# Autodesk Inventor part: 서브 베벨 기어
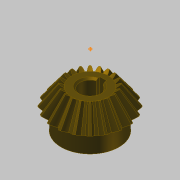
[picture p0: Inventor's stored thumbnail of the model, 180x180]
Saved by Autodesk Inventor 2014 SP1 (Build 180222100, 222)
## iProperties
Created: 2016-04
Part Number: 서브 베벨 기어
Material: 강철, 탄소
Document SubType Name: Modeling
Designer: mdu
Categories: <?xml version="1.0" encoding="UTF-16"?> <MemberInstance><Categories><FamilyTemplate><FamilyTemplateParameter ValueType="xs:double" Id="1" ObjectReferenceKey="da
Mass: 135.037 g
Surface Area: 63.6518 cm^2
Volume: 17.1585 cm^3
Density: 7.87 g/cm^3
Appearance: 얼룩무늬
CustomPartVersion: 1
Author: mdu
Revision Number: 1
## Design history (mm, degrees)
node "맨 위 점"
node "메쉬 평면2"
sketch "톱니 본체 스케치"
  geometry: L1 (0, 0)-(18.003, -31.331); L2 (18.003, -31.331)-(21.664, -28.891); L3 (21.664, -28.891)-(0, 0); L4 (20, -30)-(0, 0); L5 (10.813, -18.818)-(13.012, -17.352); L6 (18.003, -31.331)-(10.813, -18.818); L7 (21.664, -28.891)-(13.012, -17.352); L8 (0, -39.387)-(0, 6.564) reference; L9 (0, -30)-(21.664, -30)
  constraints: 16 end point, 4 point on line, 3 perpendicular, 2 collinear, 1 horizontal alignment, 1 vertical alignment
  dimensions: "d0" = 40 diameter of L4.start L8 (= da_de); "d1" = 36.00616 diameter of L1.end L8 (= da_dfe); "d2" = 43.3282 diameter of L2.end L8 (= da_dae); "d3" = 14.4 distance between parallel lines of L2 L5 (= da_b); "d4" = 28.8906 vertical distance of L2.end L1.start (= da_ve)
revolve "톱니 본체" sketch "톱니 본체 스케치" stored, may be unused: angle "d5" = 90 deg
node "시작점"
node "톱니 평면"
sketch "시작 스케치"
  geometry: L1 (0, -23.505)-(0, 10.645) reference; L2 (-0.834, -2.928)-(0.834, -2.928); A1 r 8.898 centre (-9.698, -3.713) between (-0.834, -2.928) and (-3.903, 3.04); A2 r 8.898 centre (9.698, -3.713) between (3.903, 3.04) and (0.834, -2.928); A3 r 27.357 centre (0, -24.037) between (3.903, 3.04) and (-3.903, 3.04); 1 further point
  constraints: 6 point on circle, 3 centre point, 3 symmetric about line, 2 end point, 1 coincident, 1 perpendicular, 1 other
  dimensions: "d7" = 8.89846 radius of A1 (= fd_rr); "d8" = 9.69794 horizontal distance of point (0, -24.037) A1.centre (= fd_x); "d9" = 20.32439 vertical distance of point (0, -24.037) A1.centre (= fd_y); "d57" = 27.35701 radius of A3 (= 0.5 x fd_dva + 0.3 x da_he); "d58" = 21.10901 distance from line of A3.centre L2 (= 0.5 x fd_dva - 1.12 x da_he)
node "끝점"
  node "끝 평면"
sketch "3D 스케치 오른쪽"
  node "Helical Curve Right" dims "d65" = 229.90621 (computed from da_dm, da_delta, da_beta), "d66" = 31.5, "d67" = 40 (= da_de), "d68" = -5.88003 (= -da_delta), "d69" = 12.16458 (computed from fd_loft, da_delta)
node "끝 평면 오른쪽"
sketch "끝 스케치 오른쪽"
  geometry: L1 (0, -22.649)-(0, 12.15) reference; L2 (-0.497, -1.72)-(0.497, -1.72); A1 r 5.299 centre (-5.775, -2.187) between (-0.497, -1.72) and (-2.324, 1.834); A2 r 5.299 centre (5.775, -2.187) between (2.324, 1.834) and (0.497, -1.72); A3 r 16.291 centre (0, -14.29) between (2.324, 1.834) and (-2.324, 1.834); 1 further point
  constraints: 6 point on circle, 3 centre point, 3 symmetric about line, 2 end point, 1 coincident, 1 perpendicular, 1 other
  dimensions: "d70" = 5.77526 horizontal distance of A3.centre A1.centre (computed from fd_x, fd_ratio); "d71" = 12.10346 vertical distance of point (0, -14.29) A1.centre (computed from fd_y, fd_ratio); "d72" = 5.29916 radius of A1 (computed from fd_rr, fd_ratio); "d73" = 12.57071 distance from line of point (0, -14.29) L2 (computed from d58, fd_ratio); "d74" = 16.29149 radius of A3 (computed from d57, fd_ratio)
feature "로프트 오른쪽" sketch "끝 스케치 오른쪽" dims "d75" = 0, "d77" = 0, "d79" = 0, "d80" = 90 deg, "d85" = 20, "d92" = 90 deg, "d93" = 90 deg, "da_teethtype" = 0 [user parameter]
sketch "3D 스케치 왼쪽"
  node "Helical Curve Left" dims "d26" = 229.90621 (computed from da_dm, da_delta, da_beta), "d27" = 12.16458 (computed from fd_loft, da_delta), "d28" = 40 (= da_de), "d29" = -5.88003 (= -da_delta)
node "끝 평면 왼쪽"
sketch "끝 스케치 왼쪽" dims "d56" = 10.82768 (derived)
  geometry: L1 (0, -35.087)-(0, 18.089) reference; L2 (-0.497, -1.716)-(0.497, -1.716); A1 r 5.299 centre (-5.775, -2.183) between (-0.497, -1.716) and (-2.324, 1.838); A2 r 5.299 centre (5.775, -2.183) between (2.324, 1.838) and (0.497, -1.716); A3 r 16.291 centre (0, -14.287) between (2.324, 1.838) and (-2.324, 1.838); 2 further points; 1 other entity
  constraints: 6 point on circle, 3 centre point, 3 symmetric about line, 2 end point, 1 coincident, 2 other
  dimensions: "d30" = 5.29916 radius of A1 (computed from fd_rr, fd_ratio); "d31" = 5.77526 horizontal distance of point (0, -14.287) A1.centre (computed from fd_x, fd_ratio); "d32" = 12.10346 vertical distance of A1.centre point (0, -14.287) (computed from fd_y, fd_ratio); "d61" = 16.29149 radius of A3 (computed from d57, fd_ratio); "d62" = 12.57071 distance from line of point (0, -14.287) L2 (computed from d58, fd_ratio)
feature "로프트 왼쪽" sketch "끝 스케치 왼쪽" dims "d35" = 0, "d37" = 0, "d39" = 0, "d40" = 90 deg, "d84" = 10, "d90" = 90 deg, "d91" = 90 deg, "da_teethtype" = 0 [user parameter]
sketch "본체 스케치"
  geometry: L1 (0, -35.038)-(0, -19.531) reference; L2 (18.003, -31.331)-(10.813, -18.818) reference; L3 (10.813, -18.818)-(0, -18.818); L4 (18.003, -31.331)-(0, -31.331)
  constraints: 4 end point, 2 perpendicular, 2 point on line
revolve "본체 고정" sketch "본체 스케치" stored, may be unused: angle "d46" = 90 deg
feature "피치 지름" dims angle "d47" = 90 deg
sketch "스케치8"
  geometry: C1 r 17 at (0, 0); 1 further point
  constraints: 1 centre point, 1 coincident
  dimensions: "d94" = 34 diameter of C1
extrude "돌출1" join sketch "스케치8" distance "d95" = 10; taper "d96" = 0 deg
sketch "스케치9"
  geometry: 1 further point
hole "구멍1" sketch "스케치9" at (0, 0) diameter "d97" = 12; stored, may be unused: countersink angle "d101" = 90 deg, drill point angle "d103" = 118 deg; dims "d98" = 6, "d99" = 4, "d100" = 2, "d102" = 8
sketch "스케치10"
  geometry: 1 further point
sketch "스케치11"
  geometry: 1 further point
sketch "스케치12"
  geometry: L1 (-2, 5.657)-(-2, 7.8); L2 (-2, 7.8)-(2, 7.8); L3 (2, 7.8)-(2, 5.657); A1 r 6 centre (0, 0) between (-2, 5.657) and (2, 5.657) reference; 1 further point
  constraints: 6 end point, 2 parallel, 2 point on circle, 1 perpendicular, 1 vertical
  dimensions: "d104" = 4 distance of L1.end L2.end; "d105" = 13.8 dimension on A1 L2
extrude "돌출2" cut sketch "스케치12" stored distance "d106" = 7; taper "d107" = 0 deg
chamfer "모따기1" distance "d108" = 1; stored, may be unused: second distance "d109" = 2, angle "d110" = 45 deg
body "Solid1"
feature "로프트" dims "d17" = 0, "d18" = 90 deg, "d19" = 0, "d20" = 90 deg, "d89" = 0, "da_teethtype" = 0 [user parameter]
pattern_circular "원형 패턴" dims angle "d22" = 360 deg, "d88" = 0, "da_teethtype" = 0 [user parameter]
pattern_circular "원형 패턴 오른쪽" dims angle "d82" = 360 deg, "da_teethtype" = 0 [user parameter]
pattern_circular "원형 패턴 왼쪽" dims angle "d42" = 360 deg, "da_teethtype" = 0 [user parameter]
sketch "끝 스케치"
  geometry: L1 (0, -15.359)-(0, 6.983) reference; L2 (-0.497, -1.72)-(0.497, -1.72); A1 r 5.299 centre (-5.775, -2.187) between (-0.497, -1.72) and (-2.324, 1.834); A2 r 5.299 centre (5.775, -2.187) between (2.324, 1.834) and (0.497, -1.72); A3 r 16.291 centre (0, -14.29) between (2.324, 1.834) and (-2.324, 1.834); 1 further point
  constraints: 6 point on circle, 3 centre point, 3 symmetric about line, 2 end point, 1 coincident, 1 other
  dimensions: "d12" = 5.29916 radius of A1 (computed from fd_rr, fd_ratio); "d15" = 5.77526 horizontal distance of A1.centre point (0, -14.29) (computed from fd_x, fd_ratio); "d16" = 12.10346 vertical distance of A1.centre point (0, -14.29) (computed from fd_y, fd_ratio); "d59" = 16.29149 radius of A3 (computed from d57, fd_ratio); "d60" = 12.57071 distance from line of A3.centre L2 (computed from d58, fd_ratio)
sketch "Sketch6"
  geometry: L1 (20, -30)-(0, 0) reference; L2 (0, -37.8)-(0, 6.3) reference
body "Srf1"
other parameters: "da_b" = 14.4 [user parameter; used in 2 equation terms], "da_de" = 40 [user parameter; used in 4 equation terms], "da_dae" = 43.3282 [user parameter; used in 2 equation terms], "da_dfe" = 36.00616 [user parameter; used in 1 equation term], "da_le" = 36.05551 [user parameter; used in 1 equation term], "da_omega" = 90 deg [user parameter; used in 1 equation term], "da_beta" = 0 [user parameter; used in 2 equation terms], "da_delta" = 5.88003 [user parameter; used in 8 equation terms], "da_alpha" = 20 deg [user parameter; used in 2 equation terms], "da_he" = 4.4 [user parameter; used in 4 equation terms], "da_ve" = 28.8906 [user parameter; used in 1 equation term], "fd_dv" = 48.07402 (computed from da_de, da_delta) [user parameter; used in 1 equation term], "fd_dva" = 52.07402 (computed from da_dae, da_delta) [user parameter; used in 3 equation terms], "fd_dvb" = 45.1748 (computed from fd_dv, da_alpha) [user parameter; used in 2 equation terms], "da_zv" = 240.37008 [user parameter; used in 1 equation term], "fd_loft" = 14.62 (= da_b + 0.05 x da_he) [user parameter; used in 4 equation terms], "fd_ratio" = 5.95514 (computed from da_le, fd_loft) [user parameter; used in 15 equation terms], "fd_rr" = 8.89846 (computed from fd_dd, fd_dvb) [user parameter; used in 6 equation terms], "fd_angle" = 0.66075 (computed from da_zv) [user parameter; used in 4 equation terms], "fd_x1" = 1.58709 (computed from da_dvw, fd_angle) [user parameter; used in 1 equation term], "fd_y1" = 23.98456 (computed from da_dvw, fd_angle) [user parameter; used in 1 equation term], "fd_x2" = 8.11084 (computed from fd_rr, fd_angle2, fd_angle) [user parameter; used in 1 equation term], "fd_y2" = 3.66016 (computed from fd_rr, fd_angle2, fd_angle) [user parameter; used in 1 equation term], "fd_x" = 9.69794 (= fd_x1 + fd_x2) [user parameter; used in 4 equation terms], "fd_y" = 20.32439 (= fd_y1 - fd_y2) [user parameter; used in 4 equation terms], "fd_angle2" = 3.57832 (computed from fd_dvb, fd_dd, da_alpha) [user parameter; used in 2 equation terms], "fd_dd" = 48.55402 (= fd_dva - 0.8 x da_he) [user parameter; used in 2 equation terms], "da_dvw" = 48.07402 [user parameter; used in 2 equation terms], "d11" = 14.62 (= fd_loft), "da_dm" = 32.01232 [user parameter; used in 2 equation terms], "da_x" = 0 [user parameter], "da_m" = 2 [user parameter], "d48" = 0, "d49" = 0, "d50" = 90 deg (= da_omega), "d51" = 9 deg (computed from da_z), "d52" = 0, "d53" = 0, "d54" = 0
